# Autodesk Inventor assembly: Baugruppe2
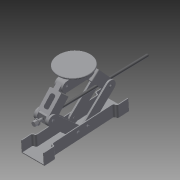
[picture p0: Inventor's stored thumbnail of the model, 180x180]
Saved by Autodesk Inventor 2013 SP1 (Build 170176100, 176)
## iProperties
Created: 2012-11
Part Number: Baugruppe2
Document SubType Name: Assembly
Designer: macuser
Author: macuser
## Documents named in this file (11)
- U:\Daten\Inventor Wagenheber weiter\Baugruppe2.iam
- U:\Daten\Inventor Wagenheber weiter\unterkasten.ipt
- U:\Daten\Inventor Wagenheber weiter\schenkl.ipt
- U:\Daten\Inventor Wagenheber weiter\hülse.ipt
- U:\Daten\Inventor Wagenheber weiter\krone.ipt
- U:\Daten\Inventor Wagenheber weiter\Teller.ipt
- U:\Daten\Inventor Wagenheber weiter\Welle.ipt
- U:\Daten\Inventor Wagenheber weiter\schenkl 2.ipt
- U:\Daten\Inventor Wagenheber weiter\bolzen unterkasten.ipt
- U:\Daten\Inventor\Content Center Files\R2013\de-DE\DIN 6799\DIN 6799 - 10 11.ipt
- U:\Daten\Inventor Wagenheber weiter\Madenschraube.ipt
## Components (36 placed, 10 different names)
1. unterkasten:1 — Passend:1, Fluchtend:1, Passend:2, Fluchtend:2, Fluchtend:3, Passend:3, Passend:4, Fluchtend:4
2. schenkl:1 — Passend:1, Fluchtend:1, Fluchtend:12, Passend:30, Passend:37, Fluchtend:17, Fluchtend:28
3. schenkl:2 — Passend:2, Fluchtend:2, Passend:25, Fluchtend:13, Passend:39, Fluchtend:19, Fluchtend:26, Passend:47
4. schenkl:3 — Fluchtend:3, Passend:3, Fluchtend:14, Passend:32, Passend:33, Passend:40, Fluchtend:20, Passend:46
5. schenkl:4 — Passend:4, Fluchtend:4, Passend:27, Passend:38, Fluchtend:18, Fluchtend:27
6. hülse:1 — Passend:24, Passend:33
7. hülse:2 — Fluchtend:12, Winkel:1, Passend:23, Passend:31, Passend:50
8. krone:1 — Passend:34, Fluchtend:15, Passend:35, Passend:36, Fluchtend:16, Passend:41, Passend:42, Passend:43, Passend:45
9. Teller:1 — Passend:36, Fluchtend:16
10. Welle:1 — Winkel:1, Passend:23, Passend:24, Passend:50
11. schenkl 2:1 — Passend:25, Fluchtend:13, Passend:30, Passend:31, Passend:35, Passend:44, Fluchtend:23, Fluchtend:24, Passend:49
12. schenkl 2:2 — Passend:27, Fluchtend:14, Passend:32, Passend:34, Fluchtend:15, Fluchtend:21, Fluchtend:22, Fluchtend:25, Passend:48
13. bolzen unterkasten:1 — Passend:37, Fluchtend:17
14. DIN 6799 10:1
15. bolzen unterkasten:2 — Passend:38, Fluchtend:18
16. bolzen unterkasten:3 — Passend:40, Fluchtend:20
17. bolzen unterkasten:4 — Passend:39, Fluchtend:19
18. DIN 6799 10:2
19. DIN 6799 10:3
20. DIN 6799 10:4
21. bolzen unterkasten:5 — Passend:45, Fluchtend:24
22. bolzen unterkasten:6 — Passend:44, Fluchtend:23
23. bolzen unterkasten:7 — Passend:41, Passend:42, Fluchtend:21
24. bolzen unterkasten:8 — Passend:43, Fluchtend:22
25. DIN 6799 10:5
26. DIN 6799 10:6
27. DIN 6799 10:7
28. DIN 6799 10:8
29. Madenschraube:1 — Fluchtend:25, Passend:46
30. Madenschraube:2 — Fluchtend:26, Passend:47
31. Madenschraube:3 — Fluchtend:27, Passend:48
32. Madenschraube:4 — Fluchtend:28, Passend:49
33. DIN 6799 10:9
34. DIN 6799 10:10
35. DIN 6799 10:11
36. DIN 6799 10:12
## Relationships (51: Mate 29, Flush 21, Angle 1)
- Passend:1 [Mate]: unterkasten:1 ↔ schenkl:1
- Fluchtend:1 [Flush]: unterkasten:1 ↔ schenkl:1
- Passend:2 [Mate]: unterkasten:1 ↔ schenkl:2
- Fluchtend:2 [Flush]: unterkasten:1 ↔ schenkl:2
- Fluchtend:3 [Flush]: unterkasten:1 ↔ schenkl:3
- Passend:3 [Mate]: unterkasten:1 ↔ schenkl:3
- Passend:4 [Mate]: unterkasten:1 ↔ schenkl:4
- Fluchtend:4 [Flush]: unterkasten:1 ↔ schenkl:4
- Fluchtend:12 [Flush]: schenkl:1 ↔ hülse:2
- Winkel:1 [Angle]: hülse:2 ↔ Welle:1
- Passend:23 [Mate]: hülse:2 ↔ Welle:1
- Passend:24 [Mate]: hülse:1 ↔ Welle:1
- Passend:25 [Mate]: schenkl:2 ↔ schenkl 2:1
- Passend:27 [Mate]: schenkl:4 ↔ schenkl 2:2
- Fluchtend:13 [Flush]: schenkl:2 ↔ schenkl 2:1
- Fluchtend:14 [Flush]: schenkl:3 ↔ schenkl 2:2
- Passend:30 [Mate]: schenkl:1 ↔ schenkl 2:1
- Passend:31 [Mate]: hülse:2 ↔ schenkl 2:1
- Passend:32 [Mate]: schenkl:3 ↔ schenkl 2:2
- Passend:33 [Mate]: schenkl:3 ↔ hülse:1
- Passend:34 [Mate]: krone:1 ↔ schenkl 2:2
- Fluchtend:15 [Flush]: krone:1 ↔ schenkl 2:2
- Passend:35 [Mate]: krone:1 ↔ schenkl 2:1
- Passend:36 [Mate]: krone:1 ↔ Teller:1
- Fluchtend:16 [Flush]: krone:1 ↔ Teller:1
- Passend:37 [Mate]: schenkl:1 ↔ bolzen unterkasten:1
- Fluchtend:17 [Flush]: schenkl:1 ↔ bolzen unterkasten:1
- Passend:38 [Mate]: schenkl:4 ↔ bolzen unterkasten:2
- Fluchtend:18 [Flush]: schenkl:4 ↔ bolzen unterkasten:2
- Passend:39 [Mate]: schenkl:2 ↔ bolzen unterkasten:4
- Fluchtend:19 [Flush]: schenkl:2 ↔ bolzen unterkasten:4
- Passend:40 [Mate]: schenkl:3 ↔ bolzen unterkasten:3
- Fluchtend:20 [Flush]: schenkl:3 ↔ bolzen unterkasten:3
- Passend:41 [Mate]: krone:1 ↔ bolzen unterkasten:7
- Passend:42 [Mate]: krone:1 ↔ bolzen unterkasten:7
- Fluchtend:21 [Flush]: schenkl 2:2 ↔ bolzen unterkasten:7
- Passend:43 [Mate]: krone:1 ↔ bolzen unterkasten:8
- Fluchtend:22 [Flush]: schenkl 2:2 ↔ bolzen unterkasten:8
- Passend:44 [Mate]: schenkl 2:1 ↔ bolzen unterkasten:6
- Fluchtend:23 [Flush]: schenkl 2:1 ↔ bolzen unterkasten:6
- Passend:45 [Mate]: krone:1 ↔ bolzen unterkasten:5
- Fluchtend:24 [Flush]: schenkl 2:1 ↔ bolzen unterkasten:5
- Fluchtend:25 [Flush]: schenkl 2:2 ↔ Madenschraube:1
- Passend:46 [Mate]: schenkl:3 ↔ Madenschraube:1
- Fluchtend:26 [Flush]: schenkl:2 ↔ Madenschraube:2
- Passend:47 [Mate]: schenkl:2 ↔ Madenschraube:2
- Fluchtend:27 [Flush]: schenkl:4 ↔ Madenschraube:3
- Fluchtend:28 [Flush]: schenkl:1 ↔ Madenschraube:4
- Passend:48 [Mate]: schenkl 2:2 ↔ Madenschraube:3
- Passend:49 [Mate]: schenkl 2:1 ↔ Madenschraube:4
- Passend:50 [Mate]: hülse:2 ↔ Welle:1
## Named parameters: winkel = -5679.57795 mm
